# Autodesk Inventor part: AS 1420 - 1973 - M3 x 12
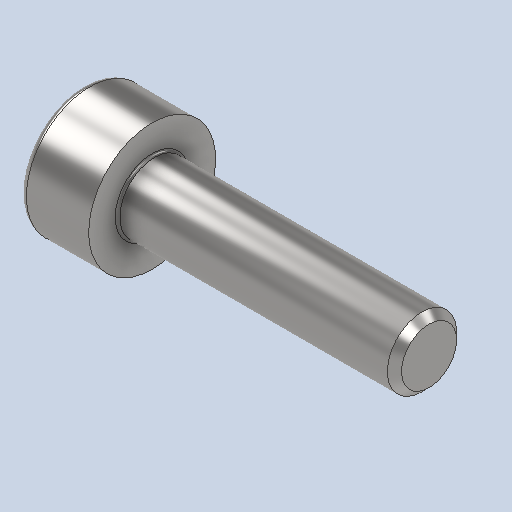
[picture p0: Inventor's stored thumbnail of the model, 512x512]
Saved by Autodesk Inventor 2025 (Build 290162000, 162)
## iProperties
Created: 2024-01
Part Number: AS 1420 - 1973 - M3 x 12
Material: Acciaio, Dolce
Description: Viti con esagono incassato metriche ISO
Document SubType Name: Modeling
Designer: Ryzen5700u
Density: 7.85 g/cm^3
Appearance: Default
Author: Ryzen5700u
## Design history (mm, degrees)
feature "Solid1"
node "Solido1"
